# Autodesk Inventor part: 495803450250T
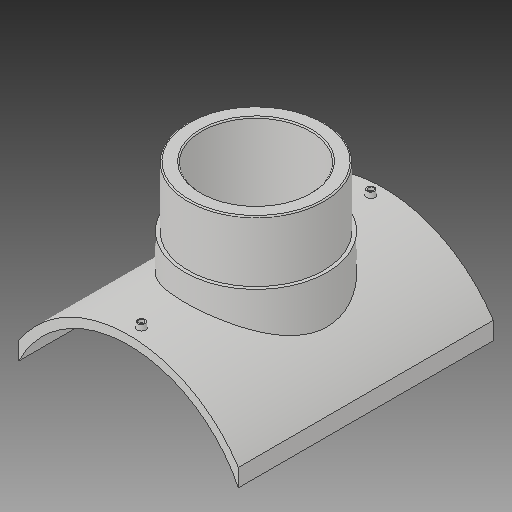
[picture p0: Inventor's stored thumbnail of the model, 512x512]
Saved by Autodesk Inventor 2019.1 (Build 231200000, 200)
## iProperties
Created: 2017-10
Part Number: 495803450250T
Material: Generic
Description: PLASSON BRANCH SADDLE 450x250
Document SubType Name: Modeling
Designer: KIM
Mass: 2754.05 g
Surface Area: 3037.44 cm^2
Volume: 2754.05 cm^3
Density: 1 g/cm^3
Appearance: Default
Author: KIM
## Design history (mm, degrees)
derived "495803.ipt"
feature "Solid1::495803.ipt"
tag "TaggingFeature1"
body "Solid1"
other parameters: "d1" = 16, "d2" = 405, "d4" = 0, "d12" = 250.6, "d13" = 14, "d14" = 211.5, "d16" = 5 deg, "d18" = 4, "d19" = 14, "d20" = 0, "d21" = 3, "d22" = 0, "d23" = 401, "d24" = 262.5, "d25" = 16, "d28" = 0, "d29" = 9.6, "d31" = 0, "d33" = 0, "d34" = 4.5, "d37" = 112, "d38" = 0, "d39" = 2.25, "B_" = 405, "x_" = 16, "D_" = 16
